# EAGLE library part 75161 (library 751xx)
75xxx DEVICE
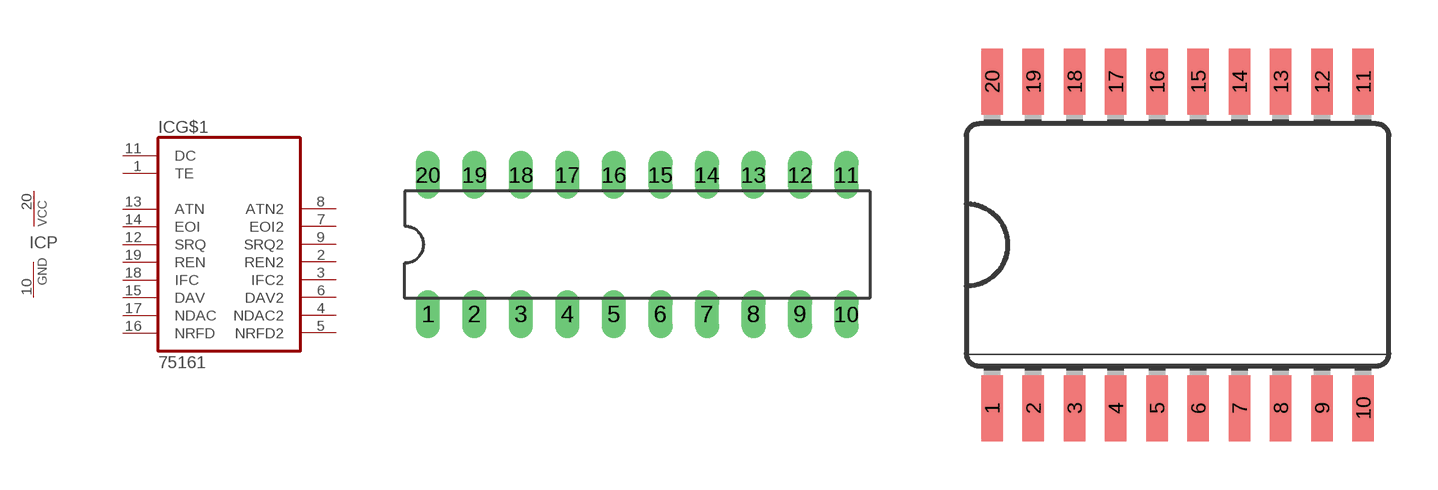
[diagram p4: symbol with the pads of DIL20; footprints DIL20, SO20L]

Designator prefix IC; gates G$1=75161 P=PWRN

## 75161P  [DIL20]
1  G$1:TE  in
2  G$1:REN2
3  G$1:IFC2
4  G$1:NDAC2
5  G$1:NRFD2
6  G$1:DAV2
7  G$1:EOI2
8  G$1:ATN2
9  G$1:SRQ2
10  P:GND  pwr
11  G$1:DC  in
12  G$1:SRQ
13  G$1:ATN
14  G$1:EOI
15  G$1:DAV
16  G$1:NRFD
17  G$1:NDAC
18  G$1:IFC
19  G$1:REN
20  P:VCC  pwr

## 75161SO  [SO20L]
Pads as for DIL20

## Footprint DIL20 (pad centres in mm)
Dual In Line Package
drill 0.813 long: 1 -11.43,-3.81; 2 -8.89,-3.81; 3 -6.35,-3.81; 4 -3.81,-3.81; 5 -1.27,-3.81; 6 1.27,-3.81; 7 3.81,-3.81; 8 6.35,-3.81; 9 8.89,-3.81; 10 11.43,-3.81; 11 11.43,3.81; 12 8.89,3.81; 13 6.35,3.81; 14 3.81,3.81; 15 1.27,3.81; 16 -1.27,3.81; 17 -3.81,3.81; 18 -6.35,3.81; 19 -8.89,3.81; 20 -11.43,3.81

## Footprint SO20L (pad centres in mm)
Small Outline package large
smd 0.66 x 2.032: 1 -5.715,-5.029; 2 -4.445,-5.029; 3 -3.175,-5.029; 4 -1.905,-5.029; 5 -0.635,-5.029; 6 0.635,-5.029; 7 1.905,-5.029; 8 3.175,-5.029; 9 4.445,-5.029; 10 5.715,-5.029; 11 5.715,5.029; 12 4.445,5.029; 13 3.175,5.029; 14 1.905,5.029; 15 0.635,5.029; 16 -0.635,5.029; 17 -1.905,5.029; 18 -3.175,5.029; 19 -4.445,5.029; 20 -5.715,5.029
